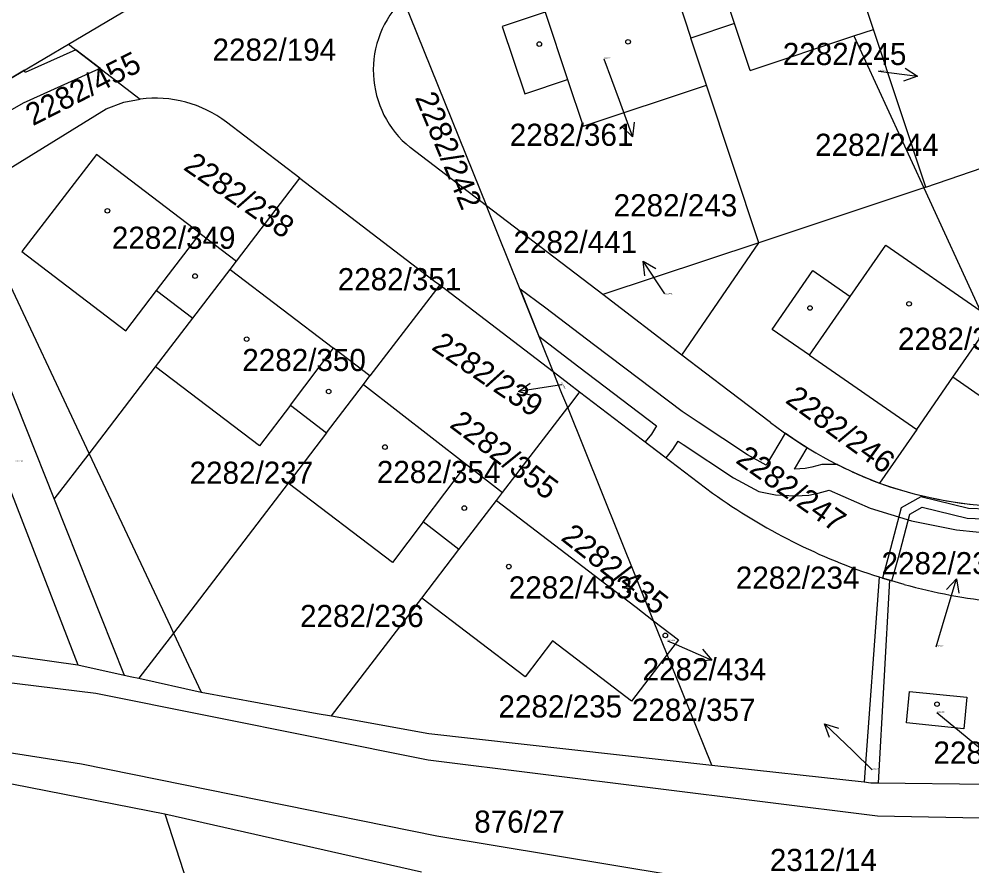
# Model space of a CAD drawing. Extents: x -785744 to -782822, y -1067550 to -1063910.
# Drawn here: x -783875 to -783802, y -1066179.1 to -1066114.1 of the extents above; entities that cross this region are included whole.
import ezdxf

# ---------------------------------------------------------------- set-up
doc = ezdxf.new("R2010")
doc.units = 0
for name, color, linetype in [('Hranice parcel', 7, 'Continuous'), ('Parcelní čísla', 7, 'Continuous'), ('Pop_ČP_popisy', 7, 'Continuous'), ('Vnitřní kresba', 7, 'Continuous'), ('Věcná břemena k části', 7, 'Continuous'), ('Značky budov', 7, 'Continuous')]:
    doc.layers.add(name, color=color, linetype=linetype)

msp = doc.modelspace()

# ---------------------------------------------------------------- linework, layer by layer
at = {"layer": 'Hranice parcel'}
for p, q in [((-783825.23, -1066110.36), (-783823.51, -1066115.55)), ((-783871.25, -1066116.02), (-783866.63, -1066113.28)), ((-783834.69, -1066113.55), (-783837.99, -1066114.65)), ((-783837.99, -1066114.65), (-783836.26, -1066119.82)), ((-783820.16, -1066114.44), (-783823.51, -1066115.55)), ((-783818.96, -1066118.03), (-783820.16, -1066114.44)), ((-783805.49, -1066127), (-783809.51, -1066114.89)), ((-783818.96, -1066118.03), (-783811.02, -1066115.39)), ((-783811.02, -1066115.39), (-783805.65, -1066127.05)), ((-783881.31, -1066121.98), (-783871.25, -1066116.02)), ((-783871.25, -1066116.02), (-783865.74, -1066120.23)), ((-783836.26, -1066119.82), (-783832.97, -1066118.73)), ((-783832.97, -1066118.73), (-783831.78, -1066122.31)), ((-783868.35, -1066120.98), (-783866.99, -1066120.48)), ((-783866.99, -1066120.48), (-783865.74, -1066120.23)), ((-783869.1, -1066124.47), (-783874.82, -1066131.93)), ((-783861.15, -1066130.54), (-783869.1, -1066124.47)), ((-783805.49, -1066127), (-783798.05, -1066124.42)), ((-783858.37, -1066132.67), (-783853.5, -1066126.3)), ((-783805.65, -1066127.05), (-783818.3, -1066131.26)), ((-783805.49, -1066127), (-783805.65, -1066127.05)), ((-783805.65, -1066127.05), (-783801.32, -1066136.44)), ((-783881.13, -1066128.85), (-783872.34, -1066150.94)), ((-783830.27, -1066135.23), (-783839.2, -1066128.41)), ((-783861.15, -1066130.54), (-783858.37, -1066132.67)), ((-783824.2, -1066139.87), (-783818.3, -1066131.26)), ((-783811.29, -1066135.37), (-783808.56, -1066131.43)), ((-783808.56, -1066131.43), (-783801.32, -1066136.44)), ((-783874.82, -1066131.93), (-783866.86, -1066138.02)), ((-783858.85, -1066133.3), (-783858.37, -1066132.67)), ((-783861.71, -1066137.04), (-783858.85, -1066133.3)), ((-783858.85, -1066133.3), (-783850.91, -1066139.35)), ((-783817.28, -1066137.9), (-783814.16, -1066133.38)), ((-783814.16, -1066133.38), (-783811.29, -1066135.37)), ((-783866.86, -1066138.02), (-783864.49, -1066134.91)), ((-783864.49, -1066134.91), (-783861.71, -1066137.04)), ((-783824.2, -1066139.87), (-783830.27, -1066135.23)), ((-783864.57, -1066140.78), (-783861.71, -1066137.04)), ((-783814.41, -1066139.89), (-783817.28, -1066137.9)), ((-783848.13, -1066141.47), (-783850.91, -1066139.35)), ((-783820.58, -1066142.63), (-783824.2, -1066139.87)), ((-783869.66, -1066147.44), (-783864.57, -1066140.78)), ((-783856.6, -1066146.84), (-783864.57, -1066140.78)), ((-783834.07, -1066141.13), (-783832.84, -1066142.08)), ((-783848.63, -1066142.13), (-783848.13, -1066141.47)), ((-783851.45, -1066145.84), (-783848.63, -1066142.13)), ((-783848.63, -1066142.13), (-783840.72, -1066148.27)), ((-783832.05, -1066142.69), (-783832.96, -1066143.89)), ((-783832.84, -1066142.08), (-783832.05, -1066142.69)), ((-783832.05, -1066142.69), (-783821.85, -1066150.47)), ((-783817.41, -1066145.05), (-783820.58, -1066142.63)), ((-783854.23, -1066143.72), (-783856.6, -1066146.84)), ((-783854.23, -1066143.72), (-783851.45, -1066145.84)), ((-783826.37, -1066160.25), (-783832.96, -1066143.89)), ((-783806.19, -1066145.57), (-783809.05, -1066149.7)), ((-783851.45, -1066145.84), (-783854.41, -1066149.71)), ((-783872.34, -1066150.94), (-783869.66, -1066147.44)), ((-783840.72, -1066148.27), (-783837.96, -1066150.42)), ((-783854.41, -1066149.71), (-783863.19, -1066161.2)), ((-783846.41, -1066155.78), (-783854.41, -1066149.71)), ((-783838.43, -1066151.04), (-783837.96, -1066150.42)), ((-783872.34, -1066150.94), (-783866.97, -1066164.42)), ((-783841.3, -1066154.8), (-783838.43, -1066151.04)), ((-783838.43, -1066151.04), (-783830.5, -1066157.08)), ((-783844.05, -1066152.66), (-783846.41, -1066155.78)), ((-783841.3, -1066154.8), (-783844.05, -1066152.66)), ((-783844.15, -1066158.52), (-783841.3, -1066154.8)), ((-783830.5, -1066157.08), (-783827.72, -1066159.21)), ((-783808.28, -1066157.15), (-783809.16, -1066172.69)), ((-783808.28, -1066157.15), (-783809.08, -1066156.9)), ((-783807.15, -1066157.47), (-783808.28, -1066157.15)), ((-783851.07, -1066167.56), (-783844.15, -1066158.52)), ((-783836.22, -1066164.55), (-783844.15, -1066158.52)), ((-783827.72, -1066159.21), (-783826.37, -1066160.25)), ((-783826.37, -1066160.25), (-783824.46, -1066161.72)), ((-783825.33, -1066162.85), (-783826.37, -1066160.25)), ((-783863.19, -1066161.2), (-783865.84, -1066164.67)), ((-783824.46, -1066161.72), (-783825.33, -1066162.85)), ((-783834.12, -1066161.8), (-783836.22, -1066164.55)), ((-783828.06, -1066166.42), (-783834.12, -1066161.8)), ((-783825.33, -1066162.85), (-783828.06, -1066166.42)), ((-783821.91, -1066171.33), (-783825.33, -1066162.85)), ((-783866.97, -1066164.42), (-783866.38, -1066164.55)), ((-783866.38, -1066164.55), (-783865.84, -1066164.67)), ((-783865.84, -1066164.67), (-783861.06, -1066165.73)), ((-783861.06, -1066165.73), (-783852.17, -1066167.36)), ((-783806.99, -1066168.09), (-783806.75, -1066165.69)), ((-783806.75, -1066165.69), (-783802.34, -1066166.11)), ((-783802.34, -1066166.11), (-783802.57, -1066168.54)), ((-783852.17, -1066167.36), (-783851.07, -1066167.56)), ((-783851.07, -1066167.56), (-783843.62, -1066168.92)), ((-783802.57, -1066168.54), (-783806.99, -1066168.09)), ((-783821.91, -1066171.33), (-783810.23, -1066172.62)), ((-783809.7, -1066172.68), (-783809.16, -1066172.69)), ((-783809.16, -1066172.69), (-783800.85, -1066172.79))]:
    msp.add_line(p, q, dxfattribs=at)
for points in [[(-783809.51, -1066114.89), (-783810.7, -1066111.29)], [(-783845.58, -1066112.56), (-783839.2, -1066128.41)], [(-783811.02, -1066115.39), (-783809.51, -1066114.89)], [(-783822.31, -1066119.16), (-783823.51, -1066115.55)], [(-783831.78, -1066122.31), (-783822.31, -1066119.16)], [(-783818.3, -1066131.26), (-783822.31, -1066119.16)], [(-783879.02, -1066127.55), (-783868.35, -1066120.98)], [(-783853.5, -1066126.3), (-783859.13, -1066122)], [(-783839.2, -1066128.41), (-783845.05, -1066123.94)], [(-783853.5, -1066126.3), (-783843.17, -1066134.19)], [(-783834.07, -1066141.13), (-783839.2, -1066128.41)], [(-783883.78, -1066129.42), (-783870.52, -1066163.63)], [(-783818.3, -1066131.26), (-783830.27, -1066135.23)], [(-783842.77, -1066134.49), (-783848.13, -1066141.47)], [(-783843.17, -1066134.19), (-783842.77, -1066134.49)], [(-783842.77, -1066134.49), (-783834.07, -1066141.13)], [(-783803.42, -1066141.57), (-783800.34, -1066137.12)], [(-783814.41, -1066139.89), (-783806.19, -1066145.57)], [(-783833.4, -1066142.81), (-783834.07, -1066141.13)], [(-783806.19, -1066145.57), (-783803.42, -1066141.57)], [(-783796.85, -1066146.14), (-783803.42, -1066141.57)], [(-783832.96, -1066143.89), (-783833.4, -1066142.81)], [(-783837.96, -1066150.42), (-783832.96, -1066143.89)], [(-783809.08, -1066156.9), (-783810.23, -1066172.62)], [(-783894.49, -1066160.27), (-783870.52, -1066163.63)], [(-783870.52, -1066163.63), (-783866.97, -1066164.42)], [(-783843.62, -1066168.92), (-783821.91, -1066171.33)], [(-783885.92, -1066170.76), (-783863.86, -1066175.06)], [(-783810.23, -1066172.62), (-783809.7, -1066172.68)], [(-783863.86, -1066175.06), (-783857.87, -1066193.55)], [(-783863.86, -1066175.06), (-783844.17, -1066179.53)]]:
    msp.add_lwpolyline(points, dxfattribs=at)
for centre, radius, start, end in [((-783840.23, -1066118.013), 7.64, 134.45489, 230.87812), ((-783864.582, -1066129.133), 8.978, 52.60846, 97.41005), ((-783797.211, -1066118.575), 33.3, 232.65802, 249.17459), ((-783798.661, -1066120.621), 30.88, 250.33942, 277.72462), ((-783794.782, -1066112.609), 46.541, 234.43804, 252.10927), ((-783795.052, -1066113.226), 45.868, 254.70698, 263.73185)]:
    msp.add_arc(centre, radius, start, end, dxfattribs=at)
at = {"layer": 'Pop_ČP_popisy'}
for p, q in [((-783809.12, -1066118.1), (-783806.144, -1066118.481)), ((-783829.02, -1066120.31), (-783827.979, -1066123.124)), ((-783825.52, -1066135.18), (-783827.172, -1066132.676)), ((-783833.78, -1066142.2), (-783836.742, -1066142.674)), ((-783804.01, -1066159.92), (-783803.148, -1066157.047)), ((-783824.65, -1066162.09), (-783821.902, -1066163.293)), ((-783811.1, -1066170.24), (-783813.258, -1066168.156)), ((-783802.32, -1066169.22), (-783800.013, -1066171.138))]:
    msp.add_line(p, q, dxfattribs=at)
for points in [[(-783830.2, -1066117.13), (-783829.02, -1066120.31)], [(-783807.073, -1066117.858), (-783806.144, -1066118.481), (-783807.2, -1066118.85)], [(-783827.857, -1066122.012), (-783827.979, -1066123.124), (-783828.795, -1066122.359)], [(-783827.039, -1066133.786), (-783827.172, -1066132.676), (-783826.204, -1066133.235)], [(-783835.676, -1066143.01), (-783836.742, -1066142.674), (-783835.834, -1066142.022)], [(-783833.42, -1066142.15), (-783833.78, -1066142.2)], [(-783803.914, -1066157.861), (-783803.148, -1066157.047), (-783802.956, -1066158.148)], [(-783804.71, -1066162.25), (-783804.01, -1066159.92)], [(-783825.3, -1066161.81), (-783824.65, -1066162.09)], [(-783822.617, -1066162.434), (-783821.902, -1066163.293), (-783823.018, -1066163.35)], [(-783804.64, -1066167.3), (-783802.32, -1066169.22)], [(-783812.886, -1066169.211), (-783813.258, -1066168.156), (-783812.192, -1066168.491)], [(-783809.6, -1066171.69), (-783811.1, -1066170.24)]]:
    msp.add_lwpolyline(points, dxfattribs=at)
at = {"layer": 'Vnitřní kresba'}
for p, q in [((-783820.16, -1066114.44), (-783821.88, -1066109.25)), ((-783834.69, -1066113.55), (-783832.97, -1066118.73)), ((-783879.02, -1066127.55), (-783869.66, -1066147.44)), ((-783864.49, -1066134.91), (-783861.15, -1066130.54)), ((-783814.41, -1066139.89), (-783811.29, -1066135.37)), ((-783854.23, -1066143.72), (-783850.91, -1066139.35)), ((-783869.66, -1066147.44), (-783863.43, -1066160.69)), ((-783844.05, -1066152.66), (-783840.72, -1066148.27)), ((-783863.43, -1066160.69), (-783863.19, -1066161.2)), ((-783863.19, -1066161.2), (-783861.06, -1066165.73))]:
    msp.add_line(p, q, dxfattribs=at)
for points in [[(-783893.51, -1066162.81), (-783869.14, -1066165.8)], [(-783869.14, -1066165.8), (-783843.65, -1066170.92)], [(-783887.37, -1066168.55), (-783870.26, -1066171.23)], [(-783870.26, -1066171.23), (-783842.99, -1066176.75)], [(-783843.65, -1066170.92), (-783809.2, -1066175.23)], [(-783809.2, -1066175.23), (-783729.43, -1066176.78)], [(-783842.99, -1066176.75), (-783824.95, -1066179.74)]]:
    msp.add_lwpolyline(points, dxfattribs=at)
at = {"layer": 'Věcná břemena k části'}
for points in [[(-783868.84, -1066117.87), (-783870.68, -1066116.45), (-783874.56, -1066118.2), (-783874.63, -1066118.02), (-783878.4, -1066120.26), (-783877.36, -1066122.02), (-783874.69, -1066120.51), (-783868.91, -1066117.9), (-783868.84, -1066117.87)], [(-783812.27, -1066148.27), (-783813.48, -1066148.26), (-783814.24, -1066148.47), (-783814.74, -1066148.57), (-783815.56, -1066148.63), (-783814.59, -1066146.98), (-783815.44, -1066146.44), (-783816.28, -1066145.87), (-783817.73, -1066148.31), (-783819.18, -1066147.52), (-783822.96, -1066145.03), (-783824.19, -1066144.2), (-783830.87, -1066139.13), (-783834.74, -1066136.2), (-783836.61, -1066134.82), (-783835.17, -1066138.41), (-783832.11, -1066140.77), (-783826.14, -1066145.29), (-783826.54, -1066145.94), (-783827.03, -1066146.52), (-783825.42, -1066147.75), (-783824.9, -1066147.12), (-783824.49, -1066146.47), (-783824.1, -1066146.73)], [(-783824.1, -1066146.73), (-783820.24, -1066149.28), (-783818.29, -1066150.34)], [(-783818.29, -1066150.34), (-783817.02, -1066150.59), (-783815.49, -1066150.68), (-783814.48, -1066150.61), (-783813.76, -1066150.47), (-783812.91, -1066150.23), (-783809.76, -1066151.63), (-783806.6, -1066152.58)], [(-783805.88, -1066150.74), (-783807.38, -1066151.59)], [(-783802.23, -1066151.64), (-783805.88, -1066150.74)], [(-783806.73, -1066152.09), (-783805.77, -1066151.54)], [(-783806.6, -1066152.58), (-783803.14, -1066153.28), (-783801.64, -1066153.44), (-783799.52, -1066153.6), (-783796.83, -1066153.5), (-783795, -1066153.34), (-783795.08, -1066151.29)], [(-783805.77, -1066151.54), (-783802.33, -1066152.39)], [(-783807.38, -1066151.59), (-783808.33, -1066155.21)], [(-783807.6, -1066155.4), (-783806.73, -1066152.09)], [(-783798.01, -1066151.81), (-783802.23, -1066151.64)], [(-783802.33, -1066152.39), (-783797.96, -1066152.56)], [(-783808.33, -1066155.21), (-783808.81, -1066156.98)], [(-783808.09, -1066157.2), (-783807.6, -1066155.4)], [(-783808.81, -1066156.98), (-783808.09, -1066157.2)]]:
    msp.add_lwpolyline(points, dxfattribs=at)
for centre, radius, start, end in [((-783798.62, -1066121.874), 29.717, 242.6555, 249.45255), ((-783798.669, -1066120.659), 30.84, 250.33031, 276.68329)]:
    msp.add_arc(centre, radius, start, end, dxfattribs=at)
at = {"layer": 'Značky budov'}
for centre in [(-783828.33, -1066115.84), (-783835.14, -1066116.01), (-783868.26, -1066128.8), (-783861.54, -1066133.81), (-783814.38, -1066136.26), (-783806.78, -1066135.94), (-783857.58, -1066138.65), (-783851.29, -1066142.67), (-783846.98, -1066146.93), (-783840.89, -1066151.61), (-783837.48, -1066156.1), (-783825.47, -1066161.38), (-783804.64, -1066166.66)]:
    msp.add_circle(centre, 0.175, dxfattribs=at)

# ---------------------------------------------------------------- texts
at = {"layer": 'Parcelní čísla'}
for s, height, p in [('2282/194', 1.7, (-783860.2, -1066117.29)), ('2282/361', 0.1, (-783830.2, -1066117.13)), ('2282/245', 0.1, (-783809.16, -1066118.09)), ('2282/244', 1.7, (-783813.99, -1066124.59)), ('2282/243', 1.7, (-783829.44, -1066129.23)), ('2282/349', 1.7, (-783867.92, -1066131.72)), ('2282/351', 1.7, (-783850.6, -1066134.9)), ('2282/441', 0.1, (-783825.51, -1066135.2)), ('2282/358', 1.7, (-783807.63, -1066139.47)), ('2282/350', 1.7, (-783857.92, -1066141.1)), ('2282/193', 0.1, (-783875.33, -1066148.05)), ('2282/237', 1.7, (-783861.96, -1066149.75)), ('2282/354', 1.7, (-783847.6, -1066149.69)), ('2282/234', 1.7, (-783820.07, -1066157.8)), ('2282/433', 1.7, (-783837.48, -1066158.55)), ('2282/236', 1.7, (-783853.49, -1066160.74)), ('2282/434', 0.1, (-783825.3, -1066161.81)), ('2282/233', 0.1, (-783804.71, -1066162.25)), ('2282/235', 1.7, (-783838.27, -1066167.68)), ('2282/445', 0.1, (-783804.64, -1066167.3)), ('2282/357', 0.1, (-783809.6, -1066171.69))]:
    msp.add_text(s, height=height, dxfattribs=at).set_placement(p)
for s, height, rotation, p in [('2282/455', 1.7, 27, (-783873.98, -1066122.32)), ('2282/242', 1.7, 292.60728, (-783844.7, -1066120.11)), ('2282/238', 1.7, 325.25595, (-783862.51, -1066125.59)), ('2282/239', 0.1, 297.80046, (-783833.47, -1066141.96)), ('2282/246', 1.7, 324, (-783816.35, -1066143.47)), ('2282/355', 1.7, 322.99749, (-783842.1, -1066145.35)), ('2282/247', 1.7, 324.68292, (-783820.16, -1066148.08)), ('2282/435', 1.7, 321.62193, (-783833.56, -1066154.01))]:
    msp.add_text(s, height=height, rotation=rotation, dxfattribs=at).set_placement(p)
at = {"layer": 'Pop_ČP_popisy'}
for s, p in [('2282/245', (-783816.468, -1066117.62)), ('2282/361', (-783837.404, -1066123.82)), ('2282/441', (-783837.121, -1066132.05)), ('2282/233', (-783808.892, -1066156.69)), ('2282/434', (-783827.218, -1066164.83)), ('2282/357', (-783828.04, -1066167.94)), ('2282/445', (-783804.908, -1066171.22)), ('876/27', (-783840.13, -1066176.52)), ('2312/14', (-783817.457, -1066179.46))]:
    msp.add_text(s, height=1.7, dxfattribs=at).set_placement(p)
msp.add_text('2282/239', height=1.7, rotation=325.99188, dxfattribs=at).set_placement((-783843.485, -1066139.397))

doc.saveas('drawing.dxf')
